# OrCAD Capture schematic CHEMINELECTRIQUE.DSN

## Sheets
1 PAGE2: size A4; title: CheminElectrique - SRO2002; rev: 1.0; note: MEZIERE Fabien - https://www.instructables.com/member/-SRO2-/
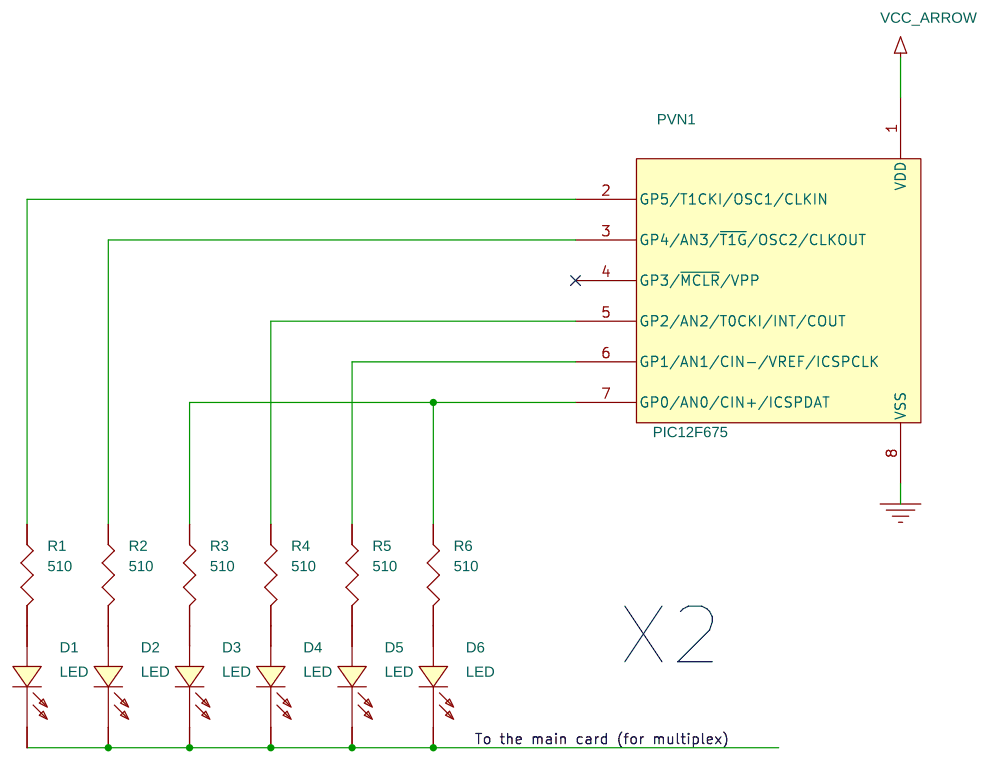
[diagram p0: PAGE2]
2 PAGE1: size A4
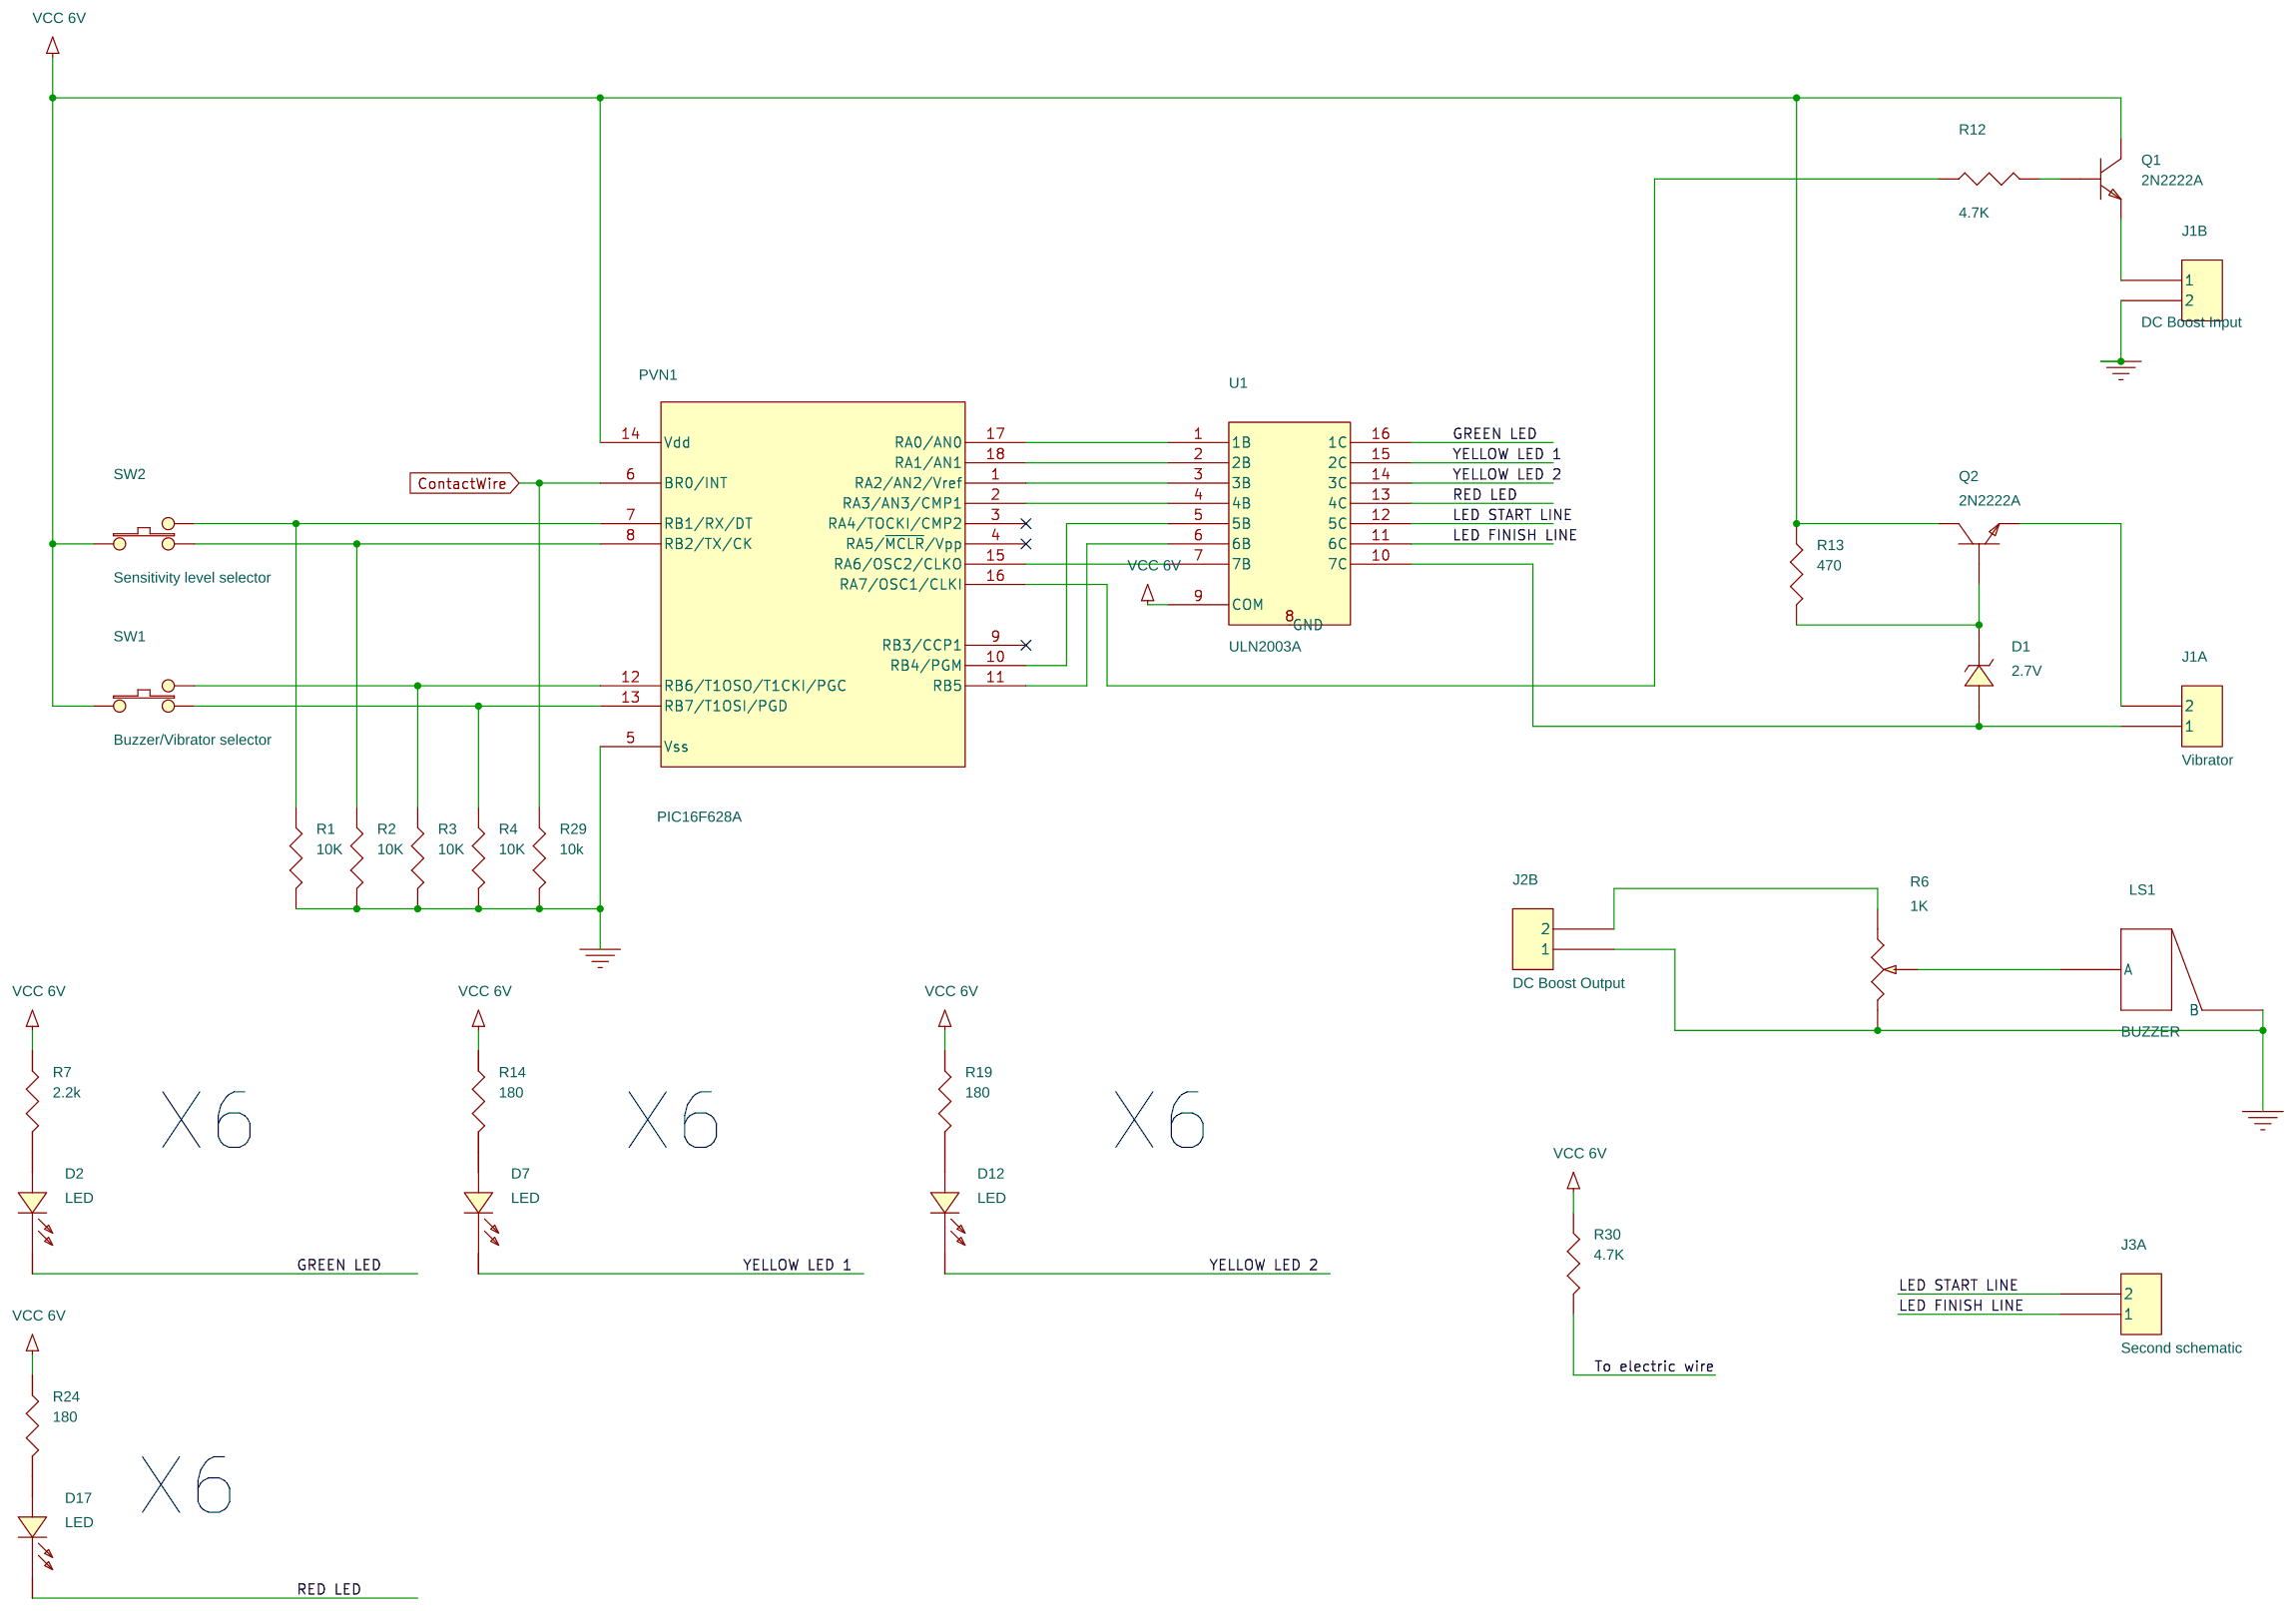
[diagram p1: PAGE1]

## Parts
sheet PAGE1
D1  2.7V
D2  LED
D7  LED
D12  LED
D17  LED
J1  Vibrator  (sections A,B)
J2  DC Boost Output  (section B)
J3  Second schematic  (section A)
LS1  BUZZER
PVN1  PIC16F628A
Q1  2N2222A
Q2  2N2222A
R1  10K
R2  10K
R3  10K
R4  10K
R6  1K
R7  2.2k
R12  4.7K
R13  470
R14  180
R19  180
R24  180
R29  10k
R30  4.7K
SW1  Buzzer/Vibrator selector
SW2  Sensitivity level selector
U1  ULN2003A
sheet PAGE2
D2#2  LED
D3  LED
D4  LED
D5  LED
D6  LED
R1#2  510
R2#2  510
R3#2  510
R4#2  510
R5  510

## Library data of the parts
D1 = DIODE_ZENER
D2 D2#2 D3-D7 D12 D17 = LED
J1-J3 = CONN_ASY_FLEX_2
LS1 = BUZZER
PVN1 = PIC16F628A_1
Q1 Q2 = 2N2222A
R1 R1#2 R2 R2#2 R3 R3#2 R4 R4#2 R5 R7 R12-R14 R19 R24 R29 R30 = R
R6 = POT
SW1 SW2 = SW_PUSHBUTTON-SPDT
U1 = ULN2003A

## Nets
GND: U1.8(GND)
VCC 6V: PVN1.14(Vdd) Q1.3(COLLECTOR) Q2.3(COLLECTOR) R7.1 R13.1 R14.1 R19.1 R24.1 R30.1 SW1.1 SW2.1 U1.9(COM)
VCC_ARROW: PVN1.1(VDD) U1.3(3B)
0: J1.2B(2) J2.1B(1) LS1.2(B) PVN1.5(GP2/AN2/T0CKI/INT/COUT) PVN1.8(VSS) R1.2 R2.1 R2.2 R3.2 R4.2 R4#2.1 R6.3(B) R29.2 SW2.3
ContactWire: PVN1.6(GP1/AN1/CIN-/VREF/ICSPCLK) R5.1 R29.1
GREEN LED: D2.2(CATHODE) U1.16(1C)
LED FINISH LINE: J3.1A(1) U1.11(6C)
LED START LINE: J3.2A(2) U1.12(5C)
RED LED: D17.2(CATHODE) U1.13(4C)
To electric wire: R30.2
To the main card (for multiplex): D1.2(CATHODE) D2#2.2(CATHODE) D3.2(CATHODE) D4.2(CATHODE) D5.2(CATHODE) D6.2(CATHODE) Q2.2(BASE) R13.2
YELLOW LED 1: D7.2(CATHODE) U1.15(2C)
YELLOW LED 2: D12.2(CATHODE) U1.14(3C)
N00396: PVN1.2(GP5/T1CKI/OSC1/CLKIN) R1#2.1 U1.4(4B)
N00403: PVN1.3(GP4/AN3/~{T1G}/OSC2/CLKOUT) R2#2.1
N00433: J2.2B(2) PVN1.7(GP0/AN0/CIN+/ICSPDAT) R1.1 R3#2.1 R6.1 SW2.2
N00490: PVN1.12(RB6/T1OSO/T1CKI/PGC) R3.1 SW1.2
N00502: PVN1.13(RB7/T1OSI/PGD) R4.1 SW1.3
N02135: J1.2A(2) Q2.1(EMITTER)
N02760: D6.1(ANODE) LS1.1(A) R6.2
N05266: J1.1B(1) Q1.1(EMITTER)
N05347: PVN1.16(RA7/OSC1/CLKI) R12.1
N05525: Q1.2(BASE) R12.2
N05925: D1.1(ANODE) J1.1A(1) R1#2.2 U1.10(7C)
N06714: PVN1.17(RA0/AN0) U1.1(1B)
N06718: PVN1.18(RA1/AN1) U1.2(2B)
N06769: PVN1.15(RA6/OSC2/CLKO) U1.7(7B)
N11366: D2.1(ANODE) R7.2
N11402: D7.1(ANODE) R14.2
N11439: D12.1(ANODE) R19.2
N11600: D17.1(ANODE) R24.2
N13241: PVN1.10(RB4/PGM) U1.5(5B)
N13256: PVN1.11(RB5) U1.6(6B)
N18343: D2#2.1(ANODE) R2#2.2
N18344: D3.1(ANODE) R3#2.2
N18346: D5.1(ANODE) R5.2
N18348: D4.1(ANODE) R4#2.2

Not connected (* = marked no-connect by the designer): PVN1 4(GP3/~{MCLR}/VPP)* 9(RB3/CCP1)*

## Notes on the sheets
sheet 1
- X2
sheet 2
- X6
- X6
- X6
- X6
